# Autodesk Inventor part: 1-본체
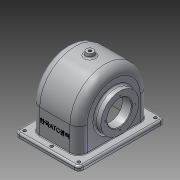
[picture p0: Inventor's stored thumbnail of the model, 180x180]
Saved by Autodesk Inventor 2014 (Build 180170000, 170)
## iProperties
Created: 2015-09
Part Number: 1-본체
Material: 알루미늄 6061
Document SubType Name: Modeling
Designer: Administrator
Density: 2.71 g/cm^3
Appearance: 알루미늄 - 평지
Mass: 737.465 g
Surface Area: 893.264 cm^2
Volume: 272.127 cm^3
Author: Administrator
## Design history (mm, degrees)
sketch "스케치1"
  geometry: L1 (-70, 0)-(70, 0); L2 (70, 0)-(70, -7); L3 (70, -7)-(-70, -7); L4 (-70, -7)-(-70, 0); L5 (-57, 40)-(-57, 0); L6 (57, 40)-(57, 0); L7 (0, 97)-(0, -7); A1 r 57 centre (0, 40) between (40.608, 0) and (-40.608, 0); 1 further point
  constraints: 14 end point, 5 point on circle, 4 point on line, 3 parallel, 2 midpoint, 2 perpendicular, 2 tangent, 1 centre point, 1 horizontal, 1 vertical, 1 vertical alignment
  dimensions: "d1" = 140 distance of L2.end L3.end; "d2" = 7 distance of L1.end L2.end; "d6" = 114 diameter of A1; "d7" = 104 distance of L7.start L7.end
extrude "돌출1" new body sketch "스케치1" stored distance "d8" = 77; taper "d9" = 0 deg
extrude "돌출2" join sketch "스케치1" stored distance "d10" = 104; taper "d11" = 0 deg
sketch "스케치2"
  geometry: L1 (-51, 40)-(51, 40); L2 (51, 40)-(51, -7); L3 (51, -7)-(-51, -7); L4 (-51, -7)-(-51, 40); L5 (70, -7)-(-70, -7) reference; A1 r 57 centre (0, 40) between (57, 40) and (-57, 40) reference; A2 r 51 centre (0, 40) between (51, 40) and (-51, 40); 1 further point
  constraints: 8 end point, 2 parallel, 2 point on circle, 1 centre point, 1 collinear, 1 horizontal, 1 midpoint, 1 perpendicular
  dimensions: "d12" = 6 radial gap between concentric circles of A1 A2
extrude "돌출3" cut sketch "스케치2" stored distance "d13" = 67; taper "d14" = 0 deg
node "작업 평면1"
sketch "스케치3"
  geometry: C1 r 28 at (40, 0); A1 r 57 centre (40, 0) between (40, -57) and (40, 57) reference; 1 further point
  constraints: 1 centre point, 1 concentric
  dimensions: "d16" = 56 diameter of C1
extrude "돌출4" join sketch "스케치3" stored distance "d17" = 66; taper "d18" = 40 deg
sketch "스케치4"
  geometry: L1 (19.5, 68)-(33.5, 79.747) reference; L2 (19.5, 68)-(19.5, 12) reference; L3 (38.5, 77.416)-(33.237, 73); L4 (35.5, 40)-(38.5, 40); L5 (38.5, 40)-(38.5, 77.416); L6 (33.237, 73)-(35.5, 73); L7 (35.5, 73)-(35.5, 40); L8 (38.5, 40)-(38.5, 97) reference; 2 further points
  constraints: 10 end point, 3 perpendicular, 1 collinear, 1 horizontal alignment, 1 midpoint, 1 parallel
  dimensions: "d19" = 5 distance between parallel lines of L1 L3; "d20" = 16 distance between parallel lines of L2 L7; "d21" = 66 diameter of L3.end L4
revolve "회전1" sketch "스케치4" stored, may be unused: angle "d22" = 90 deg
hole "구멍1" diameter "d25" = 40; stored, may be unused: countersink angle "d29" = 90 deg, drill point angle "d31" = 118 deg; dims "d23" = 10, "d24" = 10, "d26" = 6, "d27" = 4, "d28" = 2, "d30" = 16
chamfer "모따기1" distance "d32" = 1; stored, may be unused: second distance "d33" = 2, angle "d34" = 45 deg
fillet "모깎기1" dims "d35" = 3
sketch "스케치5"
  geometry: L1 (0, 0)-(28, 0); C1 r 33 at (0, 0) reference; 1 further point
  constraints: 2 end point, 1 coincident, 1 horizontal
  dimensions: "d36" = 28 distance of L1.start L1.end
hole "구멍2" sketch "스케치5" at (28, 0) diameter "d37" = 2.459; stored, may be unused: countersink angle "d41" = 90 deg, drill point angle "d43" = 118 deg; dims "d38" = 7, "d39" = 4, "d40" = 2, "d42" = 9
sketch "스케치6"
  geometry: C1 r 31 at (-40, 0); A1 r 57 centre (-40, 0) between (-40, 57) and (-40, -57) reference; 1 further point
  constraints: 1 centre point, 1 concentric
  dimensions: "d47" = 62 diameter of C1
extrude "돌출5" join sketch "스케치6" distance "d48" = 10; taper "d49" = 0 deg
hole "구멍3" diameter "d52" = 40; stored, may be unused: countersink angle "d56" = 90 deg, drill point angle "d58" = 0 deg; dims "d50" = 10, "d51" = 10, "d53" = 7, "d54" = 4, "d55" = 2, "d57" = 9
sketch "스케치7"
  geometry: L1 (0, 0)-(-24, 0); C1 r 31 at (0, 0) reference; 1 further point
  constraints: 2 end point, 1 coincident, 1 horizontal
  dimensions: "d59" = 24 distance of L1.start L1.end
hole "구멍4" sketch "스케치7" at (-24, 0) diameter "d60" = 2.459; stored, may be unused: countersink angle "d64" = 90 deg, drill point angle "d66" = 118 deg; dims "d61" = 6, "d62" = 4, "d63" = 2, "d65" = 8
chamfer "모따기2" distance "d70" = 1; stored, may be unused: second distance "d71" = 2, angle "d72" = 45 deg
fillet "모깎기2" dims "d73" = 9
fillet "모깎기3" dims "d74" = 14
fillet "모깎기4" dims "d75" = 7
node "작업 평면2"
sketch "스케치8"
  geometry: C1 r 6 at (45, -70); 1 further point
  constraints: 1 centre point, 1 coincident
  dimensions: "d77" = 12 diameter of C1
extrude "돌출6" join sketch "스케치8" stored distance "d78" = 10; taper "d79" = 10 deg
fillet "모깎기5" dims "d80" = 3
hole "구멍5" diameter "d83" = 4.459; stored, may be unused: countersink angle "d87" = 90 deg, drill point angle "d89" = 118 deg; dims "d84" = 20, "d85" = 4, "d86" = 2, "d88" = 8, "d90" = 10, "d91" = 10
sketch "스케치9"
  geometry: L1 (89, 132)-(45, 132); L2 (45, 132)-(45, 8); L3 (45, 8)-(89, 8); L4 (89, 8)-(89, 132); L5 (45, 132)-(1, 132); L6 (1, 132)-(1, 8); L7 (1, 8)-(45, 8); L8 (45, 8)-(45, 132); 2 further points
  constraints: 16 end point, 4 parallel, 2 horizontal, 2 midpoint, 2 perpendicular, 1 collinear, 1 horizontal alignment
  dimensions: "d92" = 124 distance between parallel lines of L3 L1; "d93" = 44 distance of L1.start L1.end; "d94" = 44 distance of L1.end L5.end
hole "구멍6" sketch "스케치9" at (89, 132) diameter "d95" = 5; stored, may be unused: countersink angle "d99" = 90 deg, drill point angle "d101" = 118 deg; dims "d96" = 6, "d97" = 4, "d98" = 2, "d100" = 8
fillet "모깎기6" dims "d108" = 3
fillet "모깎기7" dims "d109" = 1
sketch "스케치10"
  geometry: L1 (-0.283, -13.398)-(49.283, -13.398); L2 (49.283, -13.398)-(49.283, -20.602); L3 (49.283, -20.602)-(-0.283, -20.602); L4 (-0.283, -20.602)-(-0.283, -13.398); L5 (-20.5, -47)-(69.5, -47) reference; L6 (-14, 0)-(-14, -39) reference; 3 further points
  constraints: 2 midpoint, 2 other
  dimensions: "d110" = 30 distance from line of L5 point (-0.283, -17); "d111" = 38.5 distance from line of L6 point (24.5, -13.398)
feature "엠보싱1" sketch "스케치10" dims "d1" = 140, "d2" = 7, "d6" = 114, "d7" = 104, "d12" = 6, "d112" = 0.5, "d113" = 0
fillet "모깎기8" dims "d114" = 3
node "솔리드1"
pattern_circular "원형 패턴1" dims angle "d45" = 360 deg
pattern_circular "원형 패턴2" dims angle "d68" = 360 deg
pattern_linear "직사각형 패턴1" dims "d104" = 44 (= d93), "d107" = 124 (= d92)
other parameters: "d15" = -19
